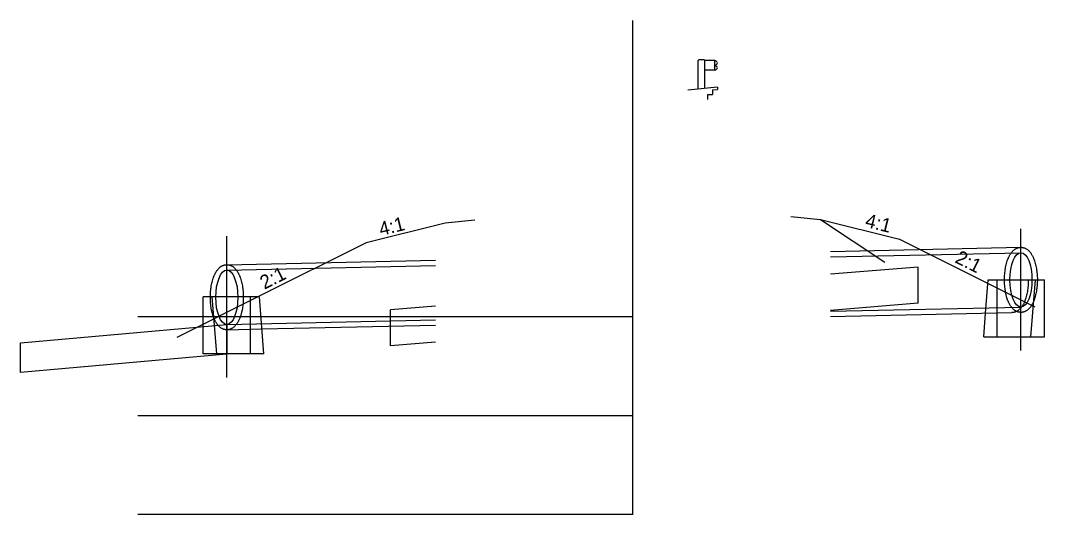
# Model space of a CAD drawing. Extents: x -65 to 655, y -121 to 151.
# Drawn here: x -65.4 to -44.67, y -6.52 to 3.48 of the extents above; entities that cross this region are included whole.
import ezdxf

# ---------------------------------------------------------------- set-up
doc = ezdxf.new("R2010")
doc.units = 0
for name, color, linetype in [('DR_P_Culvert', 7, 'Continuous'), ('DR_P_Drive_Pipe', 7, 'Continuous'), ('DR_P_Erosion_Control', 7, 'Continuous'), ('DR_P_Headwall', 7, 'Continuous'), ('DR_X_Culvert', 7, 'Continuous'), ('SH_Major_Grid_Line', 7, 'Continuous'), ('SH_Text', 7, 'Continuous'), ('TX_P_20', 7, 'Continuous'), ('XS_P_Finished_Grade', 7, 'Continuous'), ('XS_P_Pavt_Surface', 7, 'Continuous')]:
    doc.layers.add(name, color=color, linetype=linetype)

msp = doc.modelspace()

# ---------------------------------------------------------------- linework, layer by layer
at = {"layer": 'DR_P_Culvert'}
for p, q in [((-49.001, -1.193), (-45.145, -1.108)), ((-49.001, -1.301), (-45.145, -1.217)), ((-61.223, -1.46), (-57.001, -1.368)), ((-61.223, -1.569), (-57.001, -1.476)), ((-49.001, -2.401), (-45.145, -2.317)), ((-49.001, -2.51), (-45.328, -2.43)), ((-61.223, -2.669), (-57.001, -2.576)), ((-60.511, -2.76), (-57.001, -2.684)), ((-61.223, -2.777), (-60.511, -2.76))]:
    msp.add_line(p, q, dxfattribs=at)
for centre, major_axis in [((-45.145, -1.767), (0, 0.55)), ((-61.223, -2.119), (0, -0.55))]:
    msp.add_ellipse(centre, major_axis=major_axis, ratio=0.406586, dxfattribs=at)
for points in [[(-44.812, -1.767), (-44.812, -1.806), (-44.814, -1.845), (-44.82, -1.922), (-44.825, -1.959), (-44.837, -2.032), (-44.845, -2.067), (-44.863, -2.134), (-44.873, -2.166), (-44.892, -2.212), (-44.899, -2.227), (-44.913, -2.255), (-44.92, -2.268), (-44.936, -2.294), (-44.944, -2.306), (-44.962, -2.33), (-44.971, -2.341), (-44.992, -2.362), (-45.003, -2.371), (-45.026, -2.389), (-45.039, -2.397), (-45.06, -2.407), (-45.067, -2.41), (-45.082, -2.416), (-45.089, -2.418), (-45.105, -2.422), (-45.112, -2.423), (-45.129, -2.425), (-45.137, -2.426), (-45.145, -2.426), (-45.153, -2.426), (-45.161, -2.425), (-45.177, -2.423), (-45.185, -2.422), (-45.2, -2.418), (-45.208, -2.416), (-45.223, -2.41), (-45.23, -2.407), (-45.25, -2.397), (-45.263, -2.389), (-45.287, -2.371), (-45.298, -2.362), (-45.318, -2.341), (-45.328, -2.33), (-45.346, -2.306), (-45.354, -2.294), (-45.37, -2.268), (-45.377, -2.255), (-45.391, -2.227), (-45.397, -2.212), (-45.416, -2.166), (-45.427, -2.134), (-45.445, -2.067), (-45.453, -2.032), (-45.465, -1.959), (-45.469, -1.922), (-45.476, -1.845), (-45.477, -1.806), (-45.477, -1.727), (-45.476, -1.688), (-45.469, -1.612), (-45.465, -1.575), (-45.453, -1.502), (-45.445, -1.467), (-45.427, -1.4), (-45.416, -1.367), (-45.397, -1.322), (-45.391, -1.307), (-45.377, -1.279), (-45.37, -1.265), (-45.354, -1.24), (-45.346, -1.227), (-45.328, -1.204), (-45.318, -1.193), (-45.298, -1.172), (-45.287, -1.162), (-45.263, -1.145), (-45.25, -1.137), (-45.23, -1.126), (-45.223, -1.123), (-45.208, -1.118), (-45.2, -1.116), (-45.185, -1.112), (-45.177, -1.11), (-45.161, -1.109), (-45.153, -1.108), (-45.145, -1.108)], [(-45.145, -1.108), (-45.137, -1.108), (-45.129, -1.109), (-45.112, -1.11), (-45.105, -1.112), (-45.089, -1.116), (-45.082, -1.118), (-45.067, -1.123), (-45.06, -1.126), (-45.039, -1.137), (-45.026, -1.145), (-45.003, -1.162), (-44.992, -1.172), (-44.971, -1.193), (-44.962, -1.204), (-44.944, -1.227), (-44.936, -1.24), (-44.92, -1.265), (-44.913, -1.279), (-44.899, -1.307), (-44.892, -1.322), (-44.873, -1.367), (-44.863, -1.4), (-44.845, -1.467), (-44.837, -1.502), (-44.825, -1.575), (-44.82, -1.612), (-44.814, -1.688), (-44.812, -1.727), (-44.812, -1.767), (-44.812, -1.767), (-44.812, -1.767)], [(-61.223, -2.778), (-61.215, -2.778), (-61.207, -2.777), (-61.191, -2.775), (-61.183, -2.774), (-61.168, -2.77), (-61.16, -2.768), (-61.145, -2.762), (-61.138, -2.759), (-61.118, -2.749), (-61.105, -2.741), (-61.081, -2.723), (-61.07, -2.714), (-61.05, -2.693), (-61.04, -2.682), (-61.022, -2.658), (-61.014, -2.646), (-60.998, -2.62), (-60.991, -2.607), (-60.977, -2.579), (-60.97, -2.564), (-60.952, -2.518), (-60.941, -2.486), (-60.923, -2.419), (-60.915, -2.384), (-60.903, -2.311), (-60.899, -2.274), (-60.892, -2.197), (-60.891, -2.158), (-60.891, -2.079), (-60.892, -2.04), (-60.899, -1.964), (-60.903, -1.926), (-60.915, -1.854), (-60.923, -1.819), (-60.941, -1.751), (-60.952, -1.719), (-60.97, -1.674), (-60.977, -1.659), (-60.991, -1.631), (-60.998, -1.617), (-61.014, -1.592), (-61.022, -1.579), (-61.04, -1.556), (-61.05, -1.545), (-61.07, -1.524), (-61.081, -1.514), (-61.105, -1.496), (-61.118, -1.489), (-61.138, -1.478), (-61.145, -1.475), (-61.16, -1.47), (-61.168, -1.468), (-61.183, -1.464), (-61.191, -1.462), (-61.207, -1.46), (-61.215, -1.46), (-61.231, -1.46), (-61.239, -1.46), (-61.255, -1.462), (-61.263, -1.464), (-61.279, -1.468), (-61.286, -1.47), (-61.301, -1.475), (-61.308, -1.478), (-61.329, -1.489), (-61.341, -1.496), (-61.365, -1.514), (-61.376, -1.524), (-61.397, -1.545), (-61.406, -1.556), (-61.424, -1.579), (-61.432, -1.592), (-61.448, -1.617), (-61.455, -1.631), (-61.469, -1.659), (-61.476, -1.674), (-61.494, -1.719), (-61.505, -1.751), (-61.523, -1.819), (-61.531, -1.854), (-61.543, -1.926), (-61.548, -1.964), (-61.554, -2.04), (-61.556, -2.079), (-61.556, -2.158), (-61.554, -2.197), (-61.548, -2.274), (-61.543, -2.311), (-61.531, -2.384), (-61.523, -2.419), (-61.505, -2.486), (-61.494, -2.518), (-61.476, -2.564), (-61.469, -2.579), (-61.455, -2.607), (-61.448, -2.62), (-61.432, -2.646), (-61.424, -2.658), (-61.406, -2.682), (-61.397, -2.693), (-61.376, -2.714), (-61.365, -2.723), (-61.341, -2.741), (-61.329, -2.749), (-61.308, -2.759), (-61.301, -2.762), (-61.286, -2.768), (-61.279, -2.77), (-61.263, -2.774), (-61.255, -2.775), (-61.239, -2.777), (-61.231, -2.778), (-61.223, -2.778)]]:
    msp.add_open_spline(points, degree=3, dxfattribs=at)
at = {"layer": 'DR_P_Drive_Pipe'}
for p, q in [((-51.666, 2.687), (-51.678, 2.675)), ((-51.678, 2.101), (-51.678, 2.675)), ((-51.558, 2.687), (-51.666, 2.687)), ((-51.545, 2.675), (-51.558, 2.687)), ((-51.345, 2.675), (-51.545, 2.675)), ((-51.545, 2.112), (-51.545, 2.675)), ((-51.345, 2.475), (-51.345, 2.675)), ((-51.345, 2.475), (-51.545, 2.475))]:
    msp.add_line(p, q, dxfattribs=at)
msp.add_arc((-51.34, 2.575), 0.00534, 104.758, 255.2111, dxfattribs=at)
for centre, start_param, end_param in [((-51.383, 2.625), 5.170741, 7.442412), ((-51.383, 2.525), 5.123959, 7.395663)]:
    msp.add_ellipse(centre, major_axis=(0.0936, 0), ratio=0.533903, start_param=start_param, end_param=end_param, dxfattribs=at)
at = {"layer": 'DR_P_Erosion_Control'}
msp.add_lwpolyline([(-65.401, -3.039), (-61.223, -2.669), (-61.223, -3.269), (-65.401, -3.639)], close=True, dxfattribs=at)
at = {"layer": 'DR_P_Headwall'}
for p, q in [((-45.859, -2.443), (-45.806, -1.767)), ((-45.806, -1.767), (-45.623, -1.767)), ((-45.623, -2.917), (-45.623, -1.767)), ((-45.623, -1.767), (-45.477, -1.767)), ((-45.477, -1.767), (-44.995, -1.767)), ((-44.995, -1.767), (-44.85, -1.767)), ((-44.941, -2.917), (-44.85, -1.767)), ((-44.85, -1.767), (-44.667, -1.767)), ((-44.667, -2.917), (-44.667, -1.767)), ((-61.701, -3.264), (-61.701, -2.114)), ((-61.556, -2.114), (-61.701, -2.114)), ((-60.891, -2.114), (-61.556, -2.114)), ((-61.427, -3.264), (-61.518, -2.114)), ((-60.745, -2.114), (-60.891, -2.114)), ((-60.745, -3.264), (-60.745, -2.114)), ((-60.562, -2.114), (-60.745, -2.114)), ((-60.471, -3.264), (-60.562, -2.114)), ((-45.897, -2.917), (-45.859, -2.443)), ((-45.897, -2.917), (-44.667, -2.917)), ((-60.745, -3.264), (-61.701, -3.264)), ((-60.471, -3.264), (-60.745, -3.264))]:
    msp.add_line(p, q, dxfattribs=at)
msp.add_open_spline([(-44.995, -1.767), (-44.995, -1.81), (-44.997, -1.849), (-45.003, -1.926), (-45.008, -1.963), (-45.02, -2.036), (-45.027, -2.071), (-45.046, -2.138), (-45.056, -2.17), (-45.075, -2.216), (-45.081, -2.231), (-45.095, -2.259), (-45.103, -2.272), (-45.118, -2.298), (-45.127, -2.31), (-45.145, -2.334), (-45.154, -2.345), (-45.175, -2.366), (-45.186, -2.375), (-45.209, -2.393), (-45.222, -2.401), (-45.243, -2.411), (-45.25, -2.414), (-45.264, -2.42), (-45.272, -2.422), (-45.287, -2.426), (-45.295, -2.427), (-45.311, -2.429), (-45.319, -2.43), (-45.328, -2.43)], degree=3, dxfattribs=at)
at = {"layer": 'DR_X_Culvert'}
for p, q in [((-47.227, -1.508), (-49.001, -1.651)), ((-47.227, -2.241), (-47.227, -1.508)), ((-47.227, -2.241), (-49.001, -2.384)), ((-57.001, -2.298), (-57.911, -2.372)), ((-57.911, -3.105), (-57.911, -2.372)), ((-57.001, -3.031), (-57.911, -3.105))]:
    msp.add_line(p, q, dxfattribs=at)
at = {"layer": 'SH_Major_Grid_Line'}
for p, q in [((-53.001, -6.517), (-53.001, 3.483)), ((-53.001, -6.517), (-53.001, 3.483)), ((-45.145, -2.305), (-45.145, -0.732)), ((-61.223, -3.745), (-61.223, -0.883)), ((-45.145, -3.194), (-45.145, -2.317))]:
    msp.add_line(p, q, dxfattribs=at)
at = {"layer": 'TX_P_20'}
for p, q in [((-53.001, -2.517), (-63.025, -2.517)), ((-53.001, -4.517), (-63.025, -4.517)), ((-53.001, -6.517), (-63.025, -6.517))]:
    msp.add_line(p, q, dxfattribs=at)
at = {"layer": 'XS_P_Finished_Grade'}
for p, q in [((-51.289, 2.134), (-51.889, 2.074)), ((-56.801, -0.619), (-58.401, -1.019)), ((-56.201, -0.559), (-56.801, -0.619)), ((-49.801, -0.482), (-49.201, -0.542)), ((-49.201, -0.542), (-47.601, -0.942)), ((-49.201, -0.542), (-47.897, -1.412)), ((-58.401, -1.019), (-60.592, -2.114)), ((-47.601, -0.942), (-45.81, -1.838)), ((-45.81, -1.838), (-44.864, -2.311)), ((-60.592, -2.114), (-62.234, -2.935))]:
    msp.add_line(p, q, dxfattribs=at)
at = {"layer": 'XS_P_Pavt_Surface'}
for p, q in [((-51.389, 2.08), (-51.289, 2.084)), ((-51.389, 2.08), (-51.389, 1.988)), ((-51.289, 2.134), (-51.289, 2.084)), ((-51.489, 1.984), (-51.389, 1.988)), ((-51.489, 1.984), (-51.489, 1.884))]:
    msp.add_line(p, q, dxfattribs=at)

# ---------------------------------------------------------------- texts
at = {"layer": 'SH_Text'}
for s, rotation, p in [('4:1', 14.0362, (-58.103, -0.88)), ('4:1', 345.9638, (-48.315, -0.69)), ('2:1', 333.4349, (-46.498, -1.407)), ('2:1', 26.5651, (-60.463, -1.967))]:
    msp.add_text(s, height=0.28, rotation=rotation, dxfattribs=at).set_placement(p)

doc.saveas('drawing.dxf')
